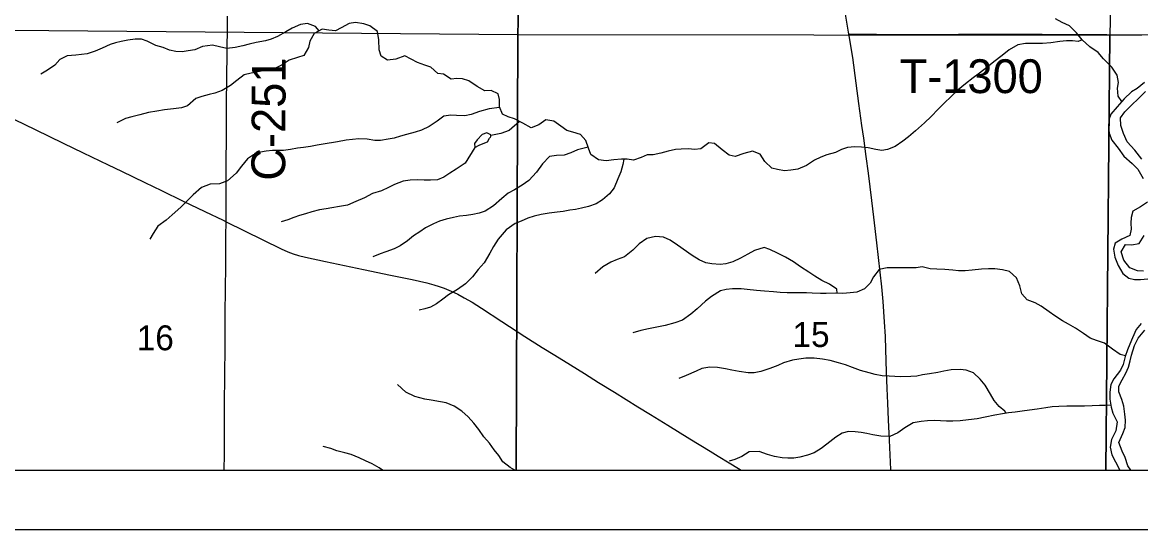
# Model space of a CAD drawing. Extents: x 0 to 34, y 0 to 22.
# Drawn here: x 5.352 to 7.232, y 14 to 14.853 of the extents above; entities that cross this region are included whole.
import ezdxf

# ---------------------------------------------------------------- set-up
doc = ezdxf.new("R2010")
doc.units = 0
for name, color, linetype in [('Default', 7, 'Continuous'), ('GM_X_County_Road', 7, 'Continuous'), ('GM_X_County_Road_Text', 7, 'Continuous'), ('GM_X_Interstate_Route', 7, 'Continuous'), ('GM_X_Major_River', 7, 'Continuous'), ('GM_X_Minor_River', 7, 'Continuous'), ('GM_X_Section', 7, 'Continuous'), ('GM_X_Section_Text', 7, 'Continuous'), ('GM_X_Township_Road', 7, 'Continuous'), ('GM_X_Township_Road_Text', 7, 'Continuous'), ('SH_Cut_Line', 7, 'Continuous'), ('SH_Data', 7, 'Continuous')]:
    doc.layers.add(name, color=color, linetype=linetype)

msp = doc.modelspace()

# ---------------------------------------------------------------- linework, layer by layer
at = {"layer": 'Default'}
for points in [[(5.1928, 14.1), (6.1826, 14.1), (6.1854, 14.8314), (5.1991, 14.84)], [(7.1737, 14.1), (8.2548, 14.1), (8.263, 14.8458), (7.1806, 14.8307)], [(6.1826, 14.1), (7.1737, 14.1), (7.1806, 14.8307), (6.1854, 14.8314)]]:
    msp.add_lwpolyline(points, close=True, dxfattribs=at)
at = {"layer": 'GM_X_County_Road'}
for points in [[(5.6949, 14.5172), (5.6949, 14.5184), (5.6949, 14.5401), (5.6949, 14.5773), (5.6949, 14.5991), (5.6951, 14.6208), (5.6953, 14.655), (5.6954, 14.686), (5.6955, 14.7077), (5.6957, 14.7294), (5.6959, 14.7449), (5.6962, 14.7666), (5.6964, 14.794), (5.6965, 14.8137), (5.6969, 14.8365), (5.6974, 14.8629)], [(6.7419, 14.833), (6.7414, 14.8361), (6.7355, 14.8697)], [(5.0787, 14.824), (5.0839, 14.8223), (5.0896, 14.8201), (5.0939, 14.8183), (5.1039, 14.8135), (5.1176, 14.8062), (5.1391, 14.7939), (5.1687, 14.7768), (5.193, 14.763), (5.2148, 14.751), (5.2479, 14.7337), (5.2784, 14.7184), (5.3035, 14.706), (5.3736, 14.6725), (5.421, 14.6494), (5.4546, 14.6331), (5.4967, 14.6131), (5.5191, 14.6023), (5.5581, 14.5833), (5.5861, 14.5697), (5.6225, 14.5522), (5.6589, 14.5347), (5.6896, 14.5198), (5.6949, 14.5172)], [(6.8124, 14.1), (6.8123, 14.1008), (6.81, 14.1505), (6.8085, 14.1846), (6.8072, 14.2126), (6.806, 14.2374), (6.8051, 14.2653), (6.8038, 14.3025), (6.8031, 14.3243), (6.8018, 14.3491), (6.7994, 14.3832), (6.7972, 14.408), (6.7916, 14.4574), (6.7889, 14.4821), (6.7836, 14.5252), (6.7804, 14.553), (6.7745, 14.5992), (6.7708, 14.6269), (6.7667, 14.6577), (6.7637, 14.6793), (6.7588, 14.7162), (6.7543, 14.7501), (6.7484, 14.7932), (6.7419, 14.833)], [(5.6917, 14.1), (5.692, 14.127), (5.6922, 14.1643), (5.6922, 14.2109), (5.6931, 14.3072), (5.6933, 14.3352), (5.6934, 14.3631), (5.6943, 14.4439), (5.6946, 14.4935), (5.6949, 14.5172)], [(5.6949, 14.5172), (5.7258, 14.502), (5.7872, 14.4719), (5.7986, 14.4668), (5.8073, 14.4634), (5.8163, 14.4607), (5.8284, 14.4577), (5.8619, 14.4507), (5.9044, 14.4415), (5.9256, 14.437), (5.9713, 14.4277), (6.0078, 14.4201), (6.032, 14.4147), (6.044, 14.4115), (6.0528, 14.4088), (6.0616, 14.4056), (6.073, 14.4008), (6.0842, 14.3956), (6.0952, 14.3898), (6.1085, 14.382), (6.1243, 14.3721), (6.1581, 14.3499), (6.1972, 14.3247), (6.226, 14.3063), (6.2472, 14.2933), (6.2736, 14.277), (6.2974, 14.2623), (6.3211, 14.2475), (6.3475, 14.2311), (6.387, 14.2063), (6.4081, 14.1932), (6.4372, 14.1753), (6.4743, 14.1527), (6.5088, 14.1317), (6.5221, 14.1236), (6.5407, 14.1124), (6.5565, 14.1026), (6.5609, 14.1)]]:
    msp.add_lwpolyline(points, dxfattribs=at)
at = {"layer": 'GM_X_Interstate_Route'}
msp.add_lwpolyline([(3.2011, 14.1), (8.2568, 14.1)], dxfattribs=at)
at = {"layer": 'GM_X_Major_River'}
for points in [[(7.2387, 14.7514), (7.2266, 14.7411), (7.2168, 14.7358), (7.2047, 14.724), (7.193, 14.7103), (7.1824, 14.6981), (7.1786, 14.6886), (7.1783, 14.6757), (7.1794, 14.6662), (7.184, 14.6545), (7.1943, 14.6409), (7.2042, 14.6276), (7.2179, 14.6151), (7.2278, 14.6057), (7.2366, 14.5901)], [(7.2342, 14.6228), (7.2224, 14.6379), (7.2098, 14.6519), (7.2033, 14.6655), (7.1991, 14.6792), (7.1987, 14.6921), (7.2059, 14.702), (7.2172, 14.7134), (7.2286, 14.7244), (7.2403, 14.7362)], [(7.2439, 14.5503), (7.2318, 14.5423), (7.2193, 14.5351), (7.2163, 14.5248), (7.2159, 14.515), (7.2163, 14.5051), (7.2141, 14.4941), (7.2004, 14.4883), (7.1895, 14.4815), (7.1868, 14.4716), (7.1891, 14.458), (7.1945, 14.4436), (7.2025, 14.4303), (7.2124, 14.4227), (7.2219, 14.4201), (7.2321, 14.4205), (7.2442, 14.4213)], [(7.237, 14.4346), (7.2271, 14.4349), (7.2142, 14.4398), (7.2043, 14.4527), (7.1997, 14.4667), (7.2069, 14.4789), (7.2172, 14.4785), (7.23, 14.4808), (7.2383, 14.4942)], [(7.2331, 14.3465), (7.2248, 14.3363), (7.2187, 14.3222), (7.2142, 14.3119), (7.2101, 14.3021), (7.2063, 14.2911), (7.2029, 14.2774), (7.1984, 14.2679), (7.1875, 14.2534), (7.1822, 14.2436), (7.1803, 14.231), (7.1807, 14.2193), (7.183, 14.206), (7.1857, 14.1958), (7.1926, 14.1814), (7.1907, 14.1658), (7.1832, 14.1514), (7.181, 14.1388), (7.184, 14.1259), (7.1901, 14.1138), (7.1973, 14.1)], [(7.2156, 14.1), (7.2106, 14.1074), (7.2064, 14.1211), (7.2011, 14.1321), (7.1954, 14.1465), (7.2021, 14.1613), (7.2063, 14.1715), (7.207, 14.1841), (7.2058, 14.1939), (7.2039, 14.2076), (7.2005, 14.2189), (7.1955, 14.2318), (7.1958, 14.2413), (7.2015, 14.2516), (7.2075, 14.263), (7.2117, 14.2732), (7.2147, 14.2839), (7.2169, 14.2934), (7.2218, 14.3097), (7.2282, 14.3215), (7.2396, 14.3352)]]:
    msp.add_lwpolyline(points, dxfattribs=at)
at = {"layer": 'GM_X_Minor_River'}
for points in [[(6.0062, 14.7909), (5.9955, 14.7962), (5.9804, 14.7908), (5.9663, 14.7889), (5.9557, 14.7957), (5.9519, 14.8063), (5.9518, 14.823), (5.9491, 14.8374), (5.9362, 14.8468), (5.9263, 14.8502), (5.9123, 14.8525), (5.9017, 14.8505), (5.8884, 14.8433), (5.8786, 14.8383), (5.8676, 14.8394), (5.8562, 14.8409), (5.8429, 14.8337), (5.8357, 14.8211), (5.8331, 14.8105), (5.8256, 14.7968), (5.815, 14.7934), (5.8009, 14.7888), (5.7888, 14.7811), (5.7756, 14.7746), (5.7615, 14.7719), (5.7483, 14.7696), (5.7369, 14.7673), (5.7251, 14.7642), (5.7127, 14.7547), (5.7021, 14.7463), (5.688, 14.738), (5.6759, 14.7337), (5.6664, 14.7311), (5.6539, 14.728), (5.6441, 14.7245), (5.6301, 14.7124), (5.6198, 14.7089), (5.6066, 14.707), (5.591, 14.7054), (5.5781, 14.7035), (5.5645, 14.7008), (5.5497, 14.6973), (5.5364, 14.6939), (5.5258, 14.6912), (5.511, 14.6839)], [(7.2008, 14.7194), (7.1944, 14.7285), (7.1936, 14.7418), (7.1951, 14.7517), (7.1928, 14.7638), (7.1837, 14.777), (7.17, 14.791), (7.1608, 14.8016), (7.1468, 14.8115), (7.1338, 14.8232), (7.1243, 14.8349), (7.1129, 14.8466), (7.1004, 14.8523), (7.0893, 14.8583)], [(5.8511, 14.8381), (5.8452, 14.8458), (5.8319, 14.8507), (5.8197, 14.8492), (5.8057, 14.843), (5.7955, 14.8366), (5.7811, 14.8285), (5.7705, 14.8243), (5.761, 14.8217), (5.7451, 14.8186), (5.7337, 14.8159), (5.7227, 14.8128), (5.7098, 14.8105), (5.6958, 14.8086), (5.6837, 14.8112), (5.6719, 14.8142), (5.6552, 14.8118), (5.6423, 14.8065), (5.6313, 14.8046), (5.6211, 14.803), (5.6101, 14.8037), (5.5995, 14.806), (5.5892, 14.8101), (5.5767, 14.8139), (5.5622, 14.821), (5.5527, 14.8241), (5.5421, 14.8244), (5.5296, 14.8228), (5.5186, 14.8205), (5.5091, 14.8179), (5.4997, 14.8152), (5.4864, 14.8094), (5.4747, 14.8041), (5.4614, 14.7999), (5.4519, 14.7983), (5.4424, 14.7975), (5.4276, 14.796), (5.4155, 14.7899), (5.4068, 14.7804), (5.3947, 14.7724), (5.3833, 14.7655)], [(7.1338, 14.8232), (7.1274, 14.8201), (7.1179, 14.8212), (7.1077, 14.8212), (7.0963, 14.8204), (7.0811, 14.8181), (7.0675, 14.8169), (7.0531, 14.8172), (7.039, 14.8168), (7.0257, 14.8145), (7.0114, 14.8065), (6.9996, 14.7966), (6.9856, 14.7863), (6.9739, 14.7768), (6.9614, 14.7673), (6.9508, 14.7593), (6.9379, 14.749), (6.9258, 14.7391), (6.9145, 14.7284), (6.9016, 14.7159), (6.8918, 14.7067), (6.8801, 14.6942), (6.8691, 14.6839), (6.854, 14.6702), (6.8422, 14.6599), (6.8324, 14.6527), (6.8195, 14.6439), (6.807, 14.6389), (6.7971, 14.6374), (6.7873, 14.6389), (6.774, 14.6415), (6.763, 14.6426), (6.7516, 14.6433), (6.7395, 14.6421), (6.7292, 14.6387), (6.7194, 14.6337), (6.705, 14.6299), (6.6948, 14.6257), (6.6838, 14.6207), (6.6705, 14.6119), (6.6561, 14.6058), (6.6444, 14.6043), (6.6334, 14.6031), (6.6216, 14.605), (6.6121, 14.6072), (6.6007, 14.6186), (6.5927, 14.6311), (6.5798, 14.6363), (6.5654, 14.6321), (6.5506, 14.6268), (6.5407, 14.6294), (6.529, 14.6381), (6.516, 14.649), (6.5062, 14.6498), (6.4929, 14.6402), (6.4823, 14.6387), (6.4724, 14.6398), (6.4599, 14.6394), (6.4504, 14.6386), (6.4379, 14.6359), (6.4254, 14.6328), (6.4129, 14.6297), (6.4027, 14.6297), (6.3928, 14.6255), (6.3795, 14.6209), (6.3693, 14.6228), (6.3594, 14.6228), (6.3465, 14.6212), (6.334, 14.62), (6.3211, 14.6215), (6.3082, 14.6306), (6.304, 14.6408), (6.2998, 14.6541), (6.2907, 14.6643), (6.2777, 14.6677), (6.2675, 14.6707), (6.2576, 14.6782), (6.2458, 14.6862), (6.2322, 14.6888), (6.2208, 14.6804), (6.2076, 14.675), (6.1939, 14.6833), (6.1794, 14.6905), (6.1688, 14.6939), (6.1593, 14.698), (6.1543, 14.7105), (6.1543, 14.7231), (6.152, 14.7325), (6.1406, 14.7378), (6.13, 14.7374), (6.1171, 14.745), (6.1026, 14.754), (6.0924, 14.7578), (6.0829, 14.7581), (6.0734, 14.7573), (6.0605, 14.7656), (6.051, 14.7668), (6.0388, 14.7773), (6.029, 14.7807), (6.0164, 14.7849), (6.0062, 14.7909)], [(6.1547, 14.7096), (6.1369, 14.7074), (6.121, 14.7025), (6.1066, 14.6979), (6.0963, 14.6956), (6.0823, 14.6959), (6.0724, 14.6966), (6.0611, 14.6947), (6.0497, 14.6867), (6.0361, 14.6775), (6.0232, 14.6711), (6.0126, 14.668), (5.9982, 14.6641), (5.988, 14.6615), (5.9773, 14.658), (5.9671, 14.6561), (5.9542, 14.6542), (5.9447, 14.6537), (5.9322, 14.656), (5.9182, 14.6567), (5.9072, 14.6559), (5.8969, 14.6544), (5.8821, 14.6517), (5.8579, 14.6478), (5.848, 14.6462), (5.8366, 14.6439), (5.8249, 14.642), (5.8147, 14.6408), (5.8033, 14.6389), (5.7915, 14.6373), (5.782, 14.6373), (5.7726, 14.6369), (5.7623, 14.6361), (5.7528, 14.6342), (5.7411, 14.6296), (5.7305, 14.6231), (5.7207, 14.6106), (5.7116, 14.5992), (5.6972, 14.5862), (5.6836, 14.5812), (5.668, 14.5804), (5.6532, 14.5747), (5.6396, 14.5629), (5.629, 14.5519), (5.6188, 14.542), (5.6044, 14.529), (5.5942, 14.5203), (5.5802, 14.51), (5.5723, 14.4974), (5.5666, 14.4879)], [(6.1883, 14.6861), (6.1708, 14.6707), (6.1564, 14.6658), (6.1396, 14.6621)], [(6.1397, 14.6634), (6.1332, 14.6668), (6.1253, 14.6638), (6.1169, 14.655), (6.1124, 14.6489), (6.1132, 14.6421), (6.1204, 14.6463), (6.1299, 14.6501), (6.134, 14.6517), (6.1374, 14.6577)], [(6.1374, 14.6577), (6.1394, 14.6598), (6.1396, 14.6608), (6.1397, 14.6634)], [(6.1132, 14.6421), (6.0966, 14.6159), (6.0818, 14.6056), (6.0708, 14.5991), (6.061, 14.5922), (6.0504, 14.5877), (6.0382, 14.5872), (6.028, 14.5872), (6.0166, 14.5876), (6.0045, 14.5871), (5.9923, 14.5856), (5.9779, 14.5802), (5.9677, 14.5749), (5.956, 14.5692), (5.9412, 14.5649), (5.9272, 14.5577), (5.9128, 14.5516), (5.8988, 14.5451), (5.8855, 14.5428), (5.8726, 14.5408), (5.8631, 14.5393), (5.8518, 14.5374), (5.8392, 14.5339), (5.8283, 14.5308), (5.8184, 14.5281), (5.8089, 14.5247), (5.7987, 14.5209), (5.7873, 14.5174)], [(6.3035, 14.6425), (6.2854, 14.6385), (6.2744, 14.6331), (6.2634, 14.6293), (6.2502, 14.6285), (6.2384, 14.6269), (6.2267, 14.6148), (6.2169, 14.6007), (6.2036, 14.587), (6.1927, 14.579), (6.1798, 14.571), (6.1692, 14.5656), (6.1586, 14.5565), (6.1446, 14.5439), (6.1306, 14.5352), (6.1203, 14.5317), (6.1097, 14.5294), (6.0991, 14.5279), (6.0874, 14.5267), (6.0771, 14.5248), (6.065, 14.5217), (6.0536, 14.5186), (6.0434, 14.5137), (6.0301, 14.5072), (6.0203, 14.5003), (6.0101, 14.4938), (5.9998, 14.4854), (5.9874, 14.4767), (5.9771, 14.4717), (5.9631, 14.4671), (5.9536, 14.4637), (5.9415, 14.4583)], [(6.3632, 14.6228), (6.3617, 14.6137), (6.3584, 14.6015), (6.3535, 14.5893), (6.3471, 14.5745), (6.3391, 14.5643), (6.3274, 14.554), (6.3172, 14.5475), (6.3039, 14.5433), (6.2922, 14.5402), (6.2823, 14.5379), (6.2724, 14.5367), (6.2614, 14.5348), (6.2516, 14.5333), (6.2379, 14.5321), (6.2243, 14.5294), (6.2129, 14.5267), (6.2023, 14.5232), (6.1909, 14.5183), (6.1807, 14.5144), (6.1659, 14.5038), (6.1523, 14.4882), (6.1444, 14.476), (6.1384, 14.4646), (6.1286, 14.4486), (6.1187, 14.4372), (6.1093, 14.4247), (6.0975, 14.4133), (6.0839, 14.4034), (6.0688, 14.3946), (6.0589, 14.3873), (6.0483, 14.3797), (6.0385, 14.374), (6.029, 14.3713), (6.0192, 14.369)], [(6.7222, 14.3973), (6.7216, 14.4042), (6.709, 14.4125), (6.6961, 14.4185), (6.6843, 14.4261), (6.6745, 14.4325), (6.6604, 14.4419), (6.6486, 14.4499), (6.6353, 14.4578), (6.622, 14.4646), (6.6091, 14.471), (6.5992, 14.474), (6.5833, 14.469), (6.572, 14.4629), (6.5595, 14.456), (6.5466, 14.4503), (6.5352, 14.4469), (6.5253, 14.4457), (6.5113, 14.4464), (6.5014, 14.4486), (6.49, 14.4535), (6.4783, 14.4607), (6.4539, 14.4781), (6.4414, 14.4864), (6.4304, 14.4913), (6.4167, 14.4924), (6.4023, 14.4893), (6.3891, 14.4802), (6.3788, 14.4699), (6.3645, 14.4585), (6.3523, 14.4539), (6.3417, 14.4493), (6.3281, 14.4417), (6.3152, 14.4302)], [(7.2067, 14.292), (7.1976, 14.2941), (7.185, 14.3035), (7.1714, 14.3133), (7.1581, 14.3178), (7.1474, 14.322), (7.1364, 14.3295), (7.1227, 14.3386), (7.1109, 14.3454), (7.1007, 14.3511), (7.0881, 14.3594), (7.0786, 14.3662), (7.0653, 14.3756), (7.0551, 14.3813), (7.0414, 14.3862), (7.0327, 14.3964), (7.0292, 14.4097), (7.0235, 14.4233), (7.0121, 14.4339), (7.0003, 14.4365), (6.9874, 14.4384), (6.9764, 14.438), (6.9646, 14.4375), (6.9491, 14.436), (6.9373, 14.4348), (6.926, 14.4351), (6.9165, 14.4363), (6.9032, 14.4374), (6.8895, 14.4377), (6.8785, 14.438), (6.8652, 14.4418), (6.855, 14.4402), (6.8398, 14.4398), (6.8064, 14.4397), (6.7928, 14.437), (6.783, 14.4248), (6.7777, 14.4142), (6.7679, 14.4047), (6.7554, 14.3993), (6.744, 14.3978), (6.7318, 14.397), (6.7197, 14.3973), (6.7038, 14.3969), (6.6939, 14.3969), (6.6803, 14.3976), (6.6704, 14.3979), (6.6488, 14.3979), (6.6381, 14.3982), (6.6264, 14.3986), (6.615, 14.3997), (6.5998, 14.4008), (6.5865, 14.4019), (6.5706, 14.4033), (6.5607, 14.4044), (6.5459, 14.4044), (6.5357, 14.4036), (6.5259, 14.4013), (6.5111, 14.3918), (6.5009, 14.3838), (6.4869, 14.3712), (6.4759, 14.3621), (6.4619, 14.3522), (6.449, 14.3476), (6.4331, 14.3433), (6.4191, 14.3403), (6.405, 14.3376), (6.3918, 14.3349), (6.3785, 14.3306)], [(7.006, 14.1954), (7.004, 14.199), (6.9945, 14.2069), (6.9858, 14.2172), (6.9797, 14.2278), (6.9709, 14.2425), (6.9625, 14.2531), (6.9511, 14.2633), (6.939, 14.2679), (6.9287, 14.2693), (6.9135, 14.2685), (6.9014, 14.2662), (6.8916, 14.2639), (6.8775, 14.2616), (6.8658, 14.26), (6.8559, 14.2581), (6.8461, 14.2573), (6.829, 14.2565), (6.8191, 14.2572), (6.8093, 14.2576), (6.7979, 14.2587), (6.7861, 14.2609), (6.7759, 14.2636), (6.7611, 14.2673), (6.7478, 14.2726), (6.736, 14.2771), (6.7246, 14.2805), (6.7106, 14.2842), (6.6973, 14.2865), (6.6832, 14.2879), (6.6692, 14.2879), (6.6574, 14.2863), (6.6472, 14.2848), (6.632, 14.2802), (6.6222, 14.276), (6.6089, 14.271), (6.5938, 14.2657), (6.5824, 14.2634), (6.5722, 14.2633), (6.5574, 14.2656), (6.5452, 14.2678), (6.5346, 14.27), (6.5209, 14.2723), (6.508, 14.273), (6.4947, 14.2707), (6.4849, 14.2661), (6.4682, 14.2592), (6.4561, 14.2542)], [(6.18, 14.1), (6.1724, 14.1046), (6.1603, 14.1137), (6.1534, 14.1243), (6.1454, 14.1341), (6.1374, 14.1451), (6.1283, 14.1557), (6.1195, 14.1682), (6.1115, 14.1788), (6.102, 14.1898), (6.0913, 14.1992), (6.0784, 14.2076), (6.0647, 14.2128), (6.0553, 14.2147), (6.0393, 14.2177), (6.0287, 14.2192), (6.012, 14.2237), (5.9972, 14.2308), (5.9827, 14.2441)], [(7.1825, 14.209), (7.1724, 14.2086), (7.1629, 14.2086), (7.1508, 14.2078), (7.1379, 14.2074), (7.1083, 14.2073), (7.0947, 14.2069), (7.0837, 14.2061), (7.0727, 14.2045), (7.0583, 14.2026), (7.0454, 14.201), (7.0329, 14.1991), (7.0215, 14.1972), (7.0101, 14.196), (6.9999, 14.1944), (6.9873, 14.1925), (6.9711, 14.1887), (6.9574, 14.1863), (6.943, 14.1844), (6.929, 14.1828), (6.9164, 14.1824), (6.9058, 14.1824), (6.8956, 14.1827), (6.8861, 14.1831), (6.874, 14.1827), (6.8633, 14.1819), (6.8501, 14.1796), (6.8361, 14.1712), (6.8243, 14.1628), (6.8107, 14.1563), (6.7955, 14.157), (6.7822, 14.1592), (6.772, 14.1615), (6.7625, 14.163), (6.7522, 14.1641), (6.7412, 14.1648), (6.7306, 14.1621), (6.72, 14.1553), (6.7049, 14.1438), (6.695, 14.1362), (6.6833, 14.1293), (6.6723, 14.1251), (6.6591, 14.1217), (6.6492, 14.1201), (6.6393, 14.1201), (6.6298, 14.1204), (6.6166, 14.1227), (6.6048, 14.1264), (6.5907, 14.1313), (6.5744, 14.1305), (6.5619, 14.1229), (6.5502, 14.1179), (6.5407, 14.1152)], [(5.9575, 14.1), (5.952, 14.1036), (5.9406, 14.1108), (5.9292, 14.1157), (5.9186, 14.1209), (5.9049, 14.1262), (5.8943, 14.1288), (5.881, 14.1326), (5.8711, 14.1363), (5.8582, 14.1397)]]:
    msp.add_lwpolyline(points, dxfattribs=at)
at = {"layer": 'GM_X_Section'}
for points in [[(5.2159, 15.85), (6.2093, 15.844), (6.1854, 14.8314), (5.1991, 14.84)], [(7.2023, 15.8508), (7.1806, 14.8307), (6.1854, 14.8314), (6.2093, 15.844), (6.6641, 15.8573)]]:
    msp.add_lwpolyline(points, close=True, dxfattribs=at)
at = {"layer": 'GM_X_Township_Road'}
msp.add_lwpolyline([(6.7419, 14.833), (6.748, 14.8329), (6.7603, 14.8328), (6.7695, 14.8327), (6.7881, 14.8325), (6.8161, 14.8323), (6.8378, 14.8323), (6.8658, 14.832), (6.9022, 14.8322), (6.926, 14.8324), (6.9497, 14.8325), (6.9989, 14.8326), (7.0236, 14.8326), (7.0428, 14.8325), (7.0665, 14.8325), (7.104, 14.8323), (7.1416, 14.8323), (7.1755, 14.8321), (7.2004, 14.8318), (7.2345, 14.8316)], dxfattribs=at)
at = {"layer": 'SH_Cut_Line'}
msp.add_lwpolyline([(2.1, 14.1), (8.2568, 14.1)], dxfattribs=at)
at = {"layer": 'SH_Data'}
for p, q in [((2.1, 14.1), (8.9, 14.1)), ((2, 14), (9, 14))]:
    msp.add_line(p, q, dxfattribs=at)

# ---------------------------------------------------------------- texts
at = {"layer": 'GM_X_County_Road_Text'}
msp.add_text('C-251', height=0.05682, rotation=89.7323, dxfattribs=at).set_placement((5.7941, 14.5863))
at = {"layer": 'GM_X_Section_Text'}
for s, p in [('15', (6.6471, 14.3069)), ('16', (5.5446, 14.3014))]:
    msp.add_text(s, height=0.04186, rotation=0, dxfattribs=at).set_placement(p)
at = {"layer": 'GM_X_Township_Road_Text'}
msp.add_text('T-1300', height=0.05682, rotation=0, dxfattribs=at).set_placement((6.8271, 14.7336))

doc.saveas('drawing.dxf')
